// Mitsubishi GX Works2 project: 36.用跳转指令做单键控制   PLC: FX3U/FX3UC

PROGRAM MAIN
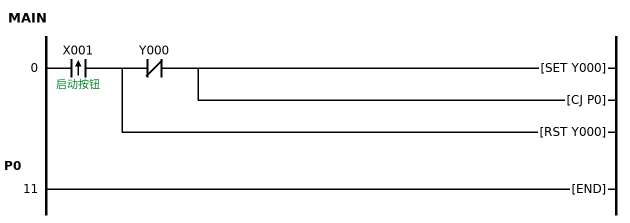
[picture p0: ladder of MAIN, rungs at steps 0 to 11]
0     LDP     X001  ; 启动按钮
      MPS
      ANI     Y000
      SET     Y000
      CJ      P0  ; 跳过停止步骤
      MPP
      RST     Y000
      P0
11    END
END_PROGRAM

// device comments not shown above
X000  ; 启动按钮
